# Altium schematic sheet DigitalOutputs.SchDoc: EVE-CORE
size A4; Organization: Ingenia Motion Control; Address1: Carrer Avila, 124, 2B; Address2: 08018 Barcelona Spain; Address3: www.ingeniamc.com; Address4: www.ingeniamc.com; Documentation: https://doc.ingeniamc.com/x/coAZBg
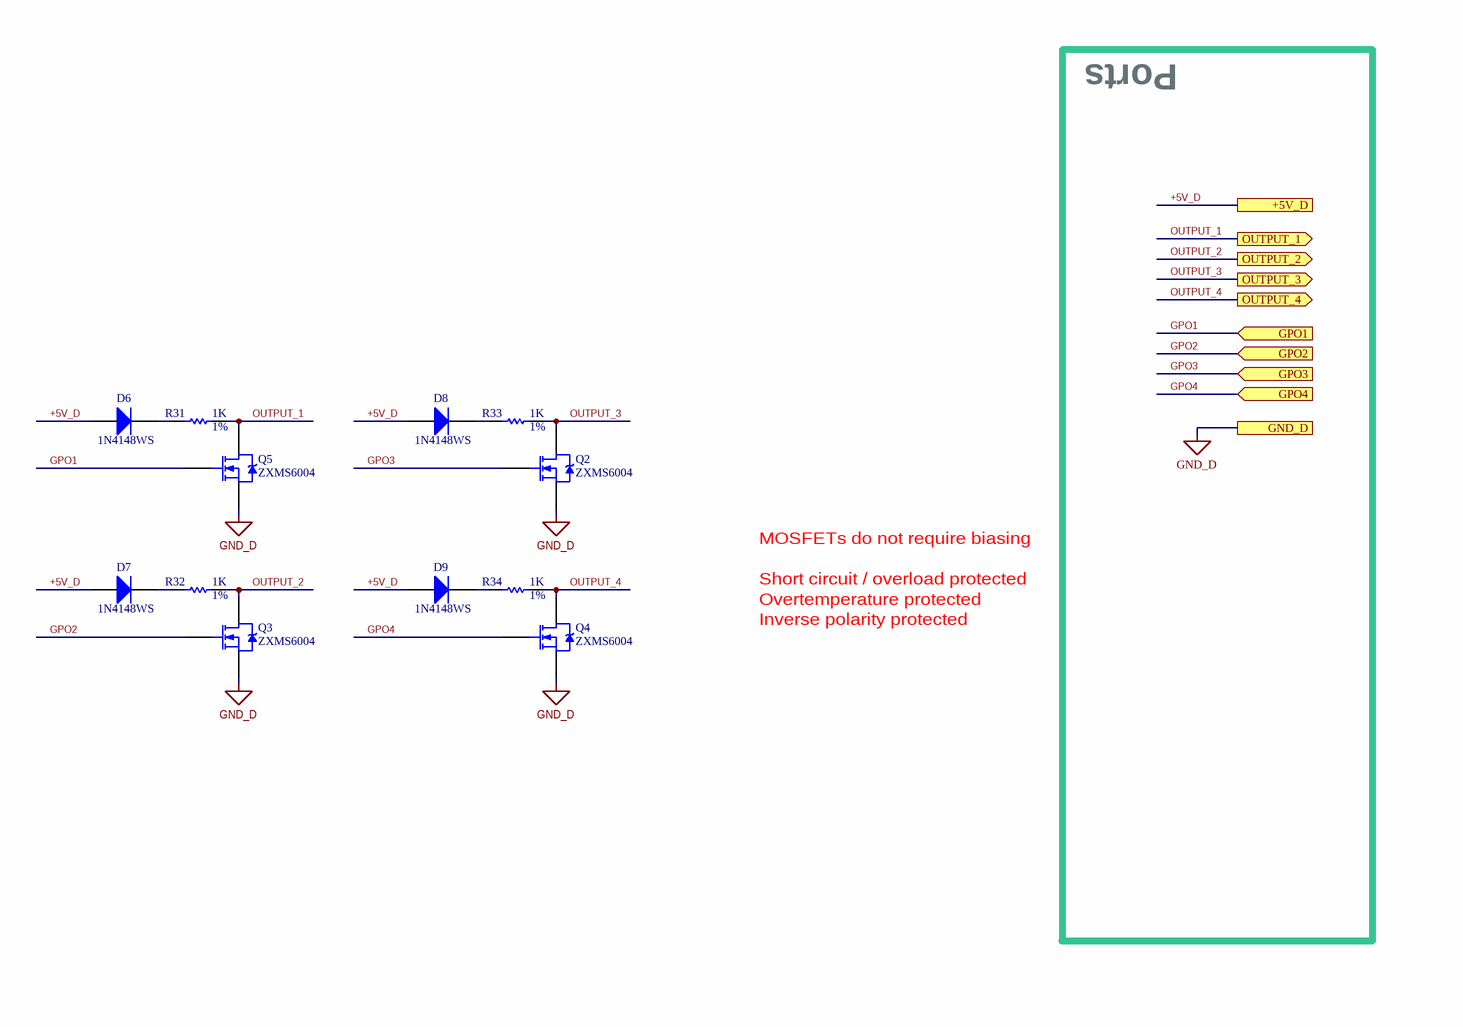
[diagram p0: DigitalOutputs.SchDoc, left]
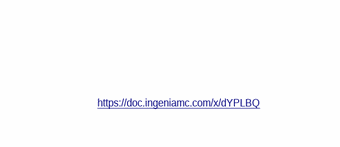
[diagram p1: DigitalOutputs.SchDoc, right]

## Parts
D6  1N4148WS  [D_SOD-323F]
D7  1N4148WS  [D_SOD-323F]
D8  1N4148WS  [D_SOD-323F]
D9  1N4148WS  [D_SOD-323F]
Q2  ZXMS6004  [SOT23-3N]
Q3  ZXMS6004  [SOT23-3N]
Q4  ZXMS6004  [SOT23-3N]
Q5  ZXMS6004  [SOT23-3N]
R31  value 1K  Tolerance: 1%  [R_0402]  (hidden comment: R_0402--1K--1%)
R32  value 1K  Tolerance: 1%  [R_0402]  (hidden comment: R_0402--1K--1%)
R33  value 1K  Tolerance: 1%  [R_0402]  (hidden comment: R_0402--1K--1%)
R34  value 1K  Tolerance: 1%  [R_0402]  (hidden comment: R_0402--1K--1%)

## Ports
+5V_D, GND_D, GPO1 (in), GPO2 (in), GPO3 (in), GPO4 (in), OUTPUT_1 (out), OUTPUT_2 (out), OUTPUT_3 (out), OUTPUT_4 (out)

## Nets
GND_D: Q2.2(S) Q3.2(S) Q4.2(S) Q5.2(S) ; port GND_D
+5V_D: D6.1(A) D7.1(A) D8.1(A) D9.1(A) ; port +5V_D
GPO1: Q5.1(G) ; port GPO1
GPO2: Q3.1(G) ; port GPO2
GPO3: Q2.1(G) ; port GPO3
GPO4: Q4.1(G) ; port GPO4
OUTPUT_1: Q5.3(D) R31.1 ; port OUTPUT_1
OUTPUT_2: Q3.3(D) R32.1 ; port OUTPUT_2
OUTPUT_3: Q2.3(D) R33.1 ; port OUTPUT_3
OUTPUT_4: Q4.3(D) R34.1 ; port OUTPUT_4
NetD6_2: D6.2(K) R31.2
NetD7_2: D7.2(K) R32.2
NetD8_2: D8.2(K) R33.2
NetD9_2: D9.2(K) R34.2

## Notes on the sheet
- Ports
- Short circuit / overload protected
- MOSFETs do not require biasing
- Inverse polarity protected
- Overtemperature protected
- https://doc.ingeniamc.com/x/dYPLBQ

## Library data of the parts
D6-D9 = 1N4148WS: Diode rectifier 75V, 150mA; ManufacturerName: Fairchild; AlternativeManufacturer: On Semiconductor; IsPreferred: 1; IngeniaID: 581; InternalStock: 0
Q2-Q5 = ZXMS6004: MOSFET N-CH, 60V, 1.3A self protected; ManufacturerName: Diodes Inc.; ManufacturerPN: ZXMS6004FFTA; IsPreferred: 1; IngeniaID: 963; InternalStock: 0
R31-R34 = R_0402[[/\]]1K[[/\]]1%: RES 1K OHM 1/16W 1% 0402 SMD; ManufacturerName: Panasonic Electronic Components; ManufacturerPN: ERJ-2RKF1001X; AlternativeManufacturer: Bourns; IsPreferred: 0; IngeniaID: 686; IsGeneric: 1; AlternativePN: CR0402-FX-1001GLF; MTBF55h: 91649788; TemperatureMaxC: 155; TemperatureMinC: -55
